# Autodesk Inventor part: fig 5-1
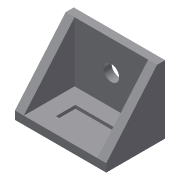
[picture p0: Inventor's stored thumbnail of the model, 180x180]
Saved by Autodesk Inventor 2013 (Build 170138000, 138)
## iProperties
Created: 2012-07
Part Number: fig 5-1
Material: Generic
Document SubType Name: Modeling
Designer: CADCIM
Density: 1 g/cm^3
Author: CADCIM
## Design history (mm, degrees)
sketch "Sketch1"
  geometry: L1 (-14.1, 7.837)-(14.1, 7.837); L2 (14.1, 7.837)-(14.1, -7.837); L3 (14.1, -7.837)-(-14.1, -7.837); L4 (-14.1, -7.837)-(-14.1, 7.837); L5 (-14.1, 7.837)-(14.1, -7.837); L6 (14.1, 7.837)-(-14.1, -7.837); 1 further point
  constraints: 12 end point, 2 midpoint, 2 parallel, 1 horizontal, 1 perpendicular
extrude "Extrusion1" new body sketch "Sketch1" distance "d0" = 2.5; taper "d1" = 0 deg
sketch "Sketch2"
  geometry: L1 (0, -20.969)-(28.201, -20.969); L2 (28.201, -20.969)-(28.201, 0); L3 (28.201, 0)-(0, 0); L4 (0, 0)-(0, -20.969); L5 (0, -20.969)-(28.201, 0); L6 (28.201, -20.969)-(0, 0); 1 further point
  constraints: 12 end point, 2 midpoint, 2 parallel, 1 horizontal, 1 perpendicular
extrude "Extrusion2" join sketch "Sketch2" distance "d2" = 2.5; taper "d3" = 0 deg
sketch "Sketch3"
  geometry: L1 (-6.24, 3)-(6.24, 3); L2 (6.24, 3)-(6.24, -3); L3 (6.24, -3)-(-6.24, -3); L4 (-6.24, -3)-(-6.24, 3); L5 (-6.24, 3)-(6.24, -3); L6 (6.24, 3)-(-6.24, -3); 1 further point
  constraints: 12 end point, 2 midpoint, 2 parallel, 1 horizontal, 1 perpendicular
extrude "Extrusion3" cut sketch "Sketch3" distance "d4" = 1; taper "d5" = 0 deg
sketch "Sketch4"
  geometry: L1 (2.5, 18.174)-(2.5, 0) reference; L2 (-18.469, 15.674)-(0, 15.674) reference; L3 (-18.469, 15.674)-(0, 0); L4 (-18.469, 15.674)-(0, 15.674); L5 (0, 0)-(0, 15.674)
  constraints: 6 end point, 1 collinear, 1 parallel
extrude "Extrusion4" join sketch "Sketch4" distance "d6" = 2.75; taper "d7" = 0 deg
mirror "Mirror1"
sketch "Sketch5"
  geometry: C1 r 2.409 at (14.1, 11.735)
  constraints: 1 centre point
extrude "Extrusion5" cut sketch "Sketch5" distance "d8" = 2.75; taper "d9" = 0 deg
body "Solid1"
